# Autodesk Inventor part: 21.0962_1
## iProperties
Created: 2011-07
Part Number: 21.0962_1
Material: Aluminum-6061
Description: L = 11.811"
Document SubType Name: Modeling
Designer: Administrator
Stock Number: 20.1088 HANDLE PROFILE 32
Density: 2.71 g/cm^3
Vendor: F
Mass: 274.342 g
Surface Area: 828.408 cm^2
Volume: 101.233 cm^3
FINISH: CLEAR ANODIZED
Author: Administrator
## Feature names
1. Extrusion1
